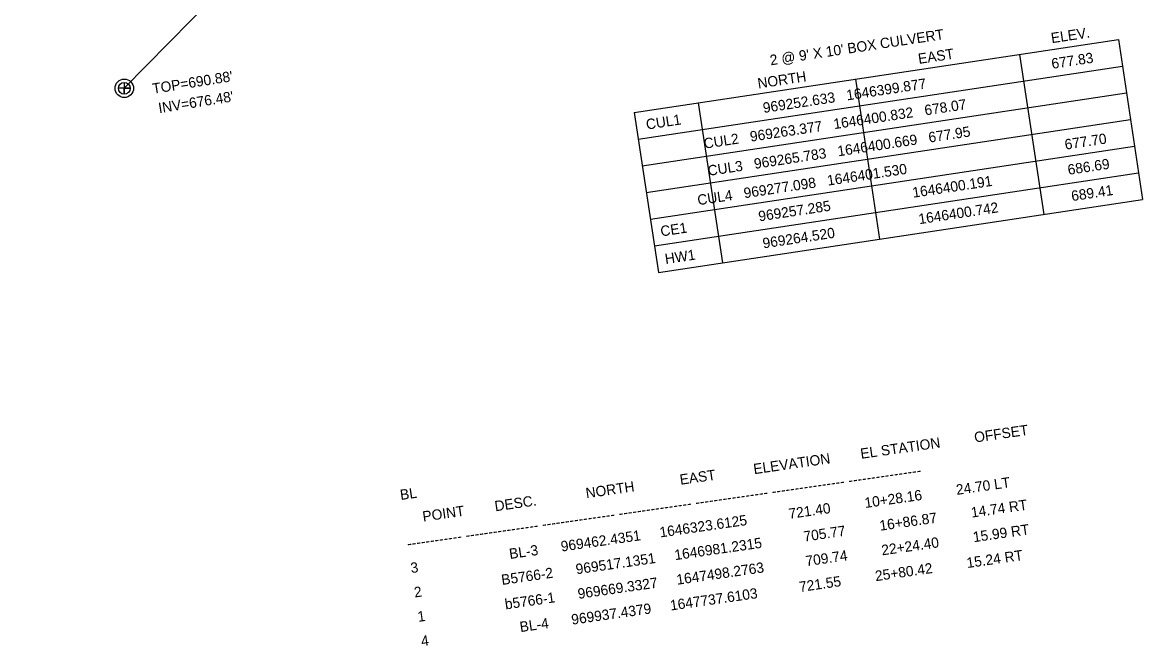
# Model space of a CAD drawing. Extents: x 1645945 to 2447332, y 713118 to 970361.
# Drawn here: x 1646352.4 to 1646678.1, y 968985.5 to 969166.9 of the extents above; entities that cross this region are included whole.
import ezdxf

# ---------------------------------------------------------------- set-up
doc = ezdxf.new("R2010")
doc.units = 0
for name, color, linetype in [('Default', 7, 'Continuous'), ('Exist Roads EOP', 7, 'Continuous'), ('Exist Structure Major Bridge WW', 7, 'Continuous'), ('Exist Structure Major Bridge WW Text', 7, 'Continuous'), ('Exist Utilities Sanitary Sewer Manhole CELL', 7, 'Continuous'), ('Exist Utilities Sanitary Sewer Manhole Top Elevation', 7, 'Continuous'), ('Exist Utilities Sanitary Sewer UG Line', 7, 'Continuous'), ('Exist Utilities Sanitary Sewer UG Line Invert Elevation', 7, 'Continuous')]:
    doc.layers.add(name, color=color, linetype=linetype)

msp = doc.modelspace()

# ---------------------------------------------------------------- linework, layer by layer
at = {"layer": 'Exist Roads EOP'}
msp.add_spline([(1646379.88, 969432.02), (1646359.09, 969426.37), (1646353.34, 969423.7), (1646346.05, 969418.75), (1646333.89, 969406.7), (1646326.81, 969393.02), (1646325.09, 969385.45), (1646325.5, 969379.16), (1646330.03, 969336.13), (1646333.52, 969294.46), (1646334.18, 969250.57), (1646332.28, 969209.59), (1646328.48, 969164.09), (1646321.21, 969122.91)], degree=3, dxfattribs=at)
at = {"layer": 'Exist Structure Major Bridge WW'}
for p, q in [((1646530.29, 969140.64), (1646671.07, 969161.88)), ((1646671.07, 969161.88), (1646678.09, 969115.34)), ((1646642.34, 969157.55), (1646649.37, 969111.01)), ((1646531.46, 969132.88), (1646672.24, 969154.13)), ((1646594.58, 969150.34), (1646601.6, 969103.8)), ((1646532.63, 969125.12), (1646673.41, 969146.37)), ((1646548.89, 969143.44), (1646555.92, 969096.9)), ((1646530.29, 969140.64), (1646537.32, 969094.09)), ((1646533.8, 969117.37), (1646674.58, 969138.61)), ((1646534.97, 969109.61), (1646675.75, 969130.86)), ((1646536.15, 969101.85), (1646676.92, 969123.1)), ((1646537.32, 969094.09), (1646678.09, 969115.34))]:
    msp.add_line(p, q, dxfattribs=at)
at = {"layer": 'Exist Utilities Sanitary Sewer Manhole CELL'}
msp.add_lwpolyline([(1646382.01, 969149.41), (1646382.01, 969145.98), (1646382.01, 969147.69), (1646383.72, 969147.69), (1646380.3, 969147.69)], dxfattribs=at)
for radius in [2.69, 1.71]:
    msp.add_circle((1646382.01, 969147.69), radius, dxfattribs=at)
at = {"layer": 'Exist Utilities Sanitary Sewer UG Line'}
msp.add_line((1646382.01, 969147.69), (1646479.6, 969247.22), dxfattribs=at)

# ---------------------------------------------------------------- texts
at = {"layer": 'Default'}
for s, p in [('     POINT        DESC.             NORTH            EAST          ELEVATION        EL STATION         OFFSET', (1646463.43, 969020.79)), ('------------ ---------------- ---------------- ---------------- ---------------- ---------------- ----------------', (1646464.45, 969013.7)), ('3                        BL-3      969462.4351     1646323.6125           721.40         10+28.16         24.70 LT', (1646465.46, 969006.6)), ('BL', (1646462.41, 969027.88)), ('2                     B5766-2      969517.1351     1646981.2315           705.77         16+86.87         14.74 RT', (1646466.48, 968999.51)), ('1                     b5766-1      969669.3327     1647498.2763           709.74         22+24.40         15.99 RT', (1646467.5, 968992.41)), ('4                        BL-4      969937.4379     1647737.6103           721.55         25+80.42         15.24 RT', (1646468.52, 968985.32))]:
    msp.add_text(s, height=3, rotation=8.1684, dxfattribs=at).set_placement(p)
at = {"layer": 'Exist Structure Major Bridge WW Text'}
for s, p in [('ELEV.', (1646651.69, 969160.81)), ("2 @ 9' X 10' BOX CULVERT", (1646569.97, 969154.37)), ('EAST', (1646613.05, 969154.78)), ('677.83', (1646651.82, 969153.35)), ('NORTH', (1646566.38, 969147.61)), ('969252.633   1646399.877', (1646567.92, 969140.5)), ('CUL2   969263.377   1646400.832   678.07', (1646550.72, 969130.11)), ('CUL1', (1646533.94, 969135.67)), ('CUL3   969265.783   1646400.669   677.95', (1646551.89, 969122.2)), ('677.70     ', (1646655.67, 969129.83)), ('686.69', (1646656.54, 969122.49)), ('CUL4   969277.098   1646401.530', (1646548.89, 969113.66)), ('1646400.191', (1646611.4, 969115.84)), ('689.41     ', (1646657.58, 969114.85)), ('969257.285', (1646566.62, 969108.95)), ('1646400.742 ', (1646613.17, 969108.14)), ('CE1', (1646538.14, 969104.57)), ('969264.520', (1646567.84, 969101.09)), ('HW1 ', (1646539.43, 969096.54))]:
    msp.add_text(s, height=3, rotation=8.5827, dxfattribs=at).set_placement(p)
at = {"layer": 'Exist Utilities Sanitary Sewer Manhole Top Elevation'}
msp.add_text("TOP=690.88'", height=3, rotation=9.0698, dxfattribs=at).set_placement((1646390.41, 969146.08))
at = {"layer": 'Exist Utilities Sanitary Sewer UG Line Invert Elevation'}
msp.add_text("INV=676.48'", height=3, rotation=9.0698, dxfattribs=at).set_placement((1646392.17, 969140.44))

doc.saveas('drawing.dxf')
